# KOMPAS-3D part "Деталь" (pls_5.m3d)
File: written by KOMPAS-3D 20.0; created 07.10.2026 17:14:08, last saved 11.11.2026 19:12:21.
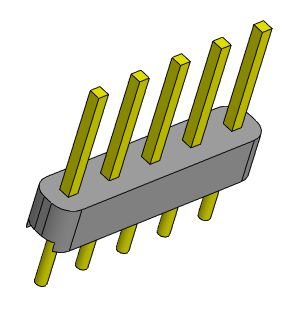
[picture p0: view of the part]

Document properties: Полное имя файла: D:\myProjects\Progect_esp32\box_compas\разъемы\pls_5.m3d

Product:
- Part/product: Деталь
    Масса: 0.000635679
  - Body: Тело 1
      Масса: 0.000660862

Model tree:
1. Эскиз:1
2. Элемент выдавливания:1
     Расстояние 1 = 2.5
3. Эскиз:2  (with: Элемент выдавливания:1)
4. Элемент выдавливания:2
     Расстояние 1 = 6
5. Массив по сетке:1  (with: Элемент выдавливания:2, Эскиз:2)  (5 pattern instances)
     Шаг 1 = 2.54; Угол раствора = 90
6. Эскиз:3  (with: Элемент выдавливания:1)
7. Элемент выдавливания:3
     Расстояние 1 = 3
8. Массив по сетке:2  (with: Элемент выдавливания:3, Эскиз:3)  (5 pattern instances)
     Шаг 1 = 2.54; Угол раствора = 90; Геометрический массив = 128
9. Эскиз:4  (with: Элемент выдавливания:1)
10. Элемент выдавливания:4
     Расстояние 2 = 12.7
11. Элемент выдавливания:5
     Расстояние 1 = 3
12. Скругление:1  (with: Элемент выдавливания:1)
     Радиус = 1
